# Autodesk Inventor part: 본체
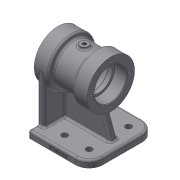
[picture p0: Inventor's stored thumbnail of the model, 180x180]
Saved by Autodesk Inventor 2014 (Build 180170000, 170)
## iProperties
Created: 2020-06
Part Number: 본체
Material: Generic
Document SubType Name: Modeling
Designer: kh
Density: 1 g/cm^3
Appearance: Default
Author: kh
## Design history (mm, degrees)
sketch "Sketch1"
  geometry: L1 (-45, -49)-(45, -49); L2 (45, -49)-(45, 49); L3 (45, 49)-(-45, 49); L4 (-45, 49)-(-45, -49); L5 (-45, -49)-(45, 49); L6 (45, -49)-(-45, 49); 1 further point
  constraints: 12 end point, 2 midpoint, 2 parallel, 1 horizontal, 1 perpendicular
  dimensions: "d0" = 98 distance between parallel lines of L1 L3; "d1" = 90 distance between parallel lines of L2 L4
extrude "Extrusion1" new body sketch "Sketch1" distance "d2" = 10; taper "d3" = 0 deg
sketch "Sketch2"
  geometry: L1 (0, 98)-(0, 0) reference; L2 (0, 98)-(10, 98) reference; L3 (80, 84)-(80, 14); L4 (80, 84)-(7, 84); L5 (7, 84)-(7, 14); L6 (7, 14)-(80, 14); 3 further points
  constraints: 8 end point, 3 perpendicular, 2 midpoint, 1 horizontal alignment, 1 parallel
  dimensions: "d4" = 80 distance from line of L3 point (0, 49); "d5" = 70 distance of L3.end L3.start
extrude "Extrusion2" join sketch "Sketch2" distance "d6" = 10; taper "d7" = 0 deg
sketch "Sketch3"
  geometry: L1 (-3.882, 90)-(-33, 10); L2 (-45, 0)-(45, 0) reference; L3 (35, 10)-(45, 10) reference; L4 (45, 10)-(-45, 10) reference; L5 (-45, 10)-(45, 10) reference; L6 (45, 10)-(35, 10) reference; L7 (-3.882, 90)-(40, 90); L8 (40, 90)-(40, 10); L9 (-33, 10)-(40, 10); 1 further point
  constraints: 8 end point, 1 collinear, 1 midpoint, 1 parallel, 1 point on line
  dimensions: "d8" = 12 distance of L1.end L4.end; "d9" = 70 deg angle of L4 L1; "d10" = 80 vertical distance of L1.start L1.end
extrude "Extrusion3" join sketch "Sketch3" stored distance "d11" = 10; taper "d12" = 0 deg
sketch "Sketch4"
  geometry: L1 (50, 115)-(28, 115); L2 (28, 115)-(28, 109); L3 (28, 109)-(-6, 109); L4 (-6, 109)-(-6, 115); L5 (-6, 115)-(-28, 115); L6 (-45, 0)-(45, 0) reference; L7 (45, 0)-(45, 10) reference; L8 (-45, 10)-(45, 10) reference; L9 (-45, 0)-(-45, 10) reference; L10 (50, 80)-(-28, 80); L11 (50, 115)-(50, 80); L12 (-28, 115)-(-28, 80); 4 further points
  constraints: 16 end point, 3 parallel, 3 perpendicular, 2 midpoint, 1 collinear, 1 horizontal, 1 point on line, 1 vertical alignment
  dimensions: "d13" = 78 distance of L5.end L1.start; "d14" = 22 distance of L1.end L1.start; "d15" = 22 distance of L5.end L4.end; "d16" = 5 distance from line of L7 L1.start; "d19" = 80 distance between parallel lines of L6 L10; "d20" = 70 diameter of L1 L10; "d21" = 70 diameter of L5 L10; "d22" = 58 diameter of L3 L10
revolve "Revolution1" sketch "Sketch4" stored, may be unused: angle "d23" = 90 deg
sketch "Sketch5"
  geometry: L1 (56, 80)-(-56, 80); L2 (-45, 0)-(45, 0) reference; L3 (50, 103.5)-(32, 103.5); L4 (32, 103.5)-(32, 100); L5 (32, 100)-(26, 100); L6 (26, 100)-(26, 103); L7 (26, 103)-(-4, 103); L8 (-4, 103)-(-4, 100); L9 (-4, 100)-(-10, 100); L10 (-10, 100)-(-10, 103.5); L11 (-10, 103.5)-(-28, 103.5); L12 (28, 51.434)-(-6, 51.434) reference; L13 (28, 51.434)-(28, 51.434) reference; L14 (-6, 51.434)-(28, 51.434) reference; L15 (-6, 51.434)-(-6, 51.434) reference; L16 (50, 45)-(50, 115) reference; L17 (35, 45.359)-(28, 45.359) reference; L18 (35, 80)-(35, 45.359) reference; L19 (45, 80)-(35, 80) reference; L20 (45, 80)-(45, 80) reference; L21 (45, 80)-(35, 80) reference; L22 (35, 45.359)-(35, 80) reference; L23 (28, 45.359)-(35, 45.359) reference; L24 (28, 45.359)-(28, 45.359) reference; L25 (-6, 45.359)-(-20.13, 45.359) reference; L26 (-6, 45.359)-(-6, 45.359) reference; L27 (-20.13, 45.359)-(-6, 45.359) reference; L28 (-20.13, 45.359)-(-20.13, 45.359) reference; L29 (-28, 45)-(-28, 115) reference; L30 (50, 103.5)-(50, 80); L31 (-28, 103.5)-(-28, 80); L32 (50, 80)-(-28, 80); 2 further points
  constraints: 26 end point, 5 perpendicular, 4 parallel, 3 midpoint, 2 point on line, 1 collinear, 1 horizontal, 1 vertical alignment
  dimensions: "d24" = 80 distance between parallel lines of L2 L1; "d25" = 47 diameter of L3 L1; "d26" = 47 diameter of L11 L1; "d27" = 46 diameter of L7 L1; "d28" = 40 diameter of L5 L1; "d29" = 40 diameter of L9 L1; "d30" = 18 distance of L3.start L3.end; "d31" = 18 distance of L10.end L11.end; "d32" = 30 distance of L6.end L7.end; "d33" = 6 distance of L4.end L5.end
revolve "Revolution2" sketch "Sketch5" stored, may be unused: angle "d34" = 90 deg
sketch "Sketch6"
  geometry: C1 r 23.5 at (0, 0) reference; 2 further points
  constraints: 1 horizontal alignment
  dimensions: "d35" = 28.5 distance of C1.centre point (28.5, 0)
hole "Hole1" sketch "Sketch6" at (28.5, 0) diameter "d36" = 3.242; stored, may be unused: countersink angle "d40" = 90 deg, drill point angle "d42" = 118 deg; dims "d37" = 10, "d38" = 4, "d39" = 2, "d41" = 12
pattern_circular "Circular Pattern1" dims angle "d44" = 360 deg
sketch "Sketch7"
  geometry: C1 r 23.5 at (0, 0) reference; 2 further points
  constraints: 1 horizontal alignment
  dimensions: "d46" = 28.5 distance of C1.centre point (-28.5, 0)
hole "Hole2" sketch "Sketch7" at (-28.5, 0) diameter "d47" = 3.242; stored, may be unused: countersink angle "d51" = 90 deg, drill point angle "d53" = 118 deg; dims "d48" = 10, "d49" = 4, "d50" = 2, "d52" = 12
pattern_circular "Circular Pattern2" dims angle "d55" = 360 deg
workplane "Work Plane1"
sketch "Sketch8"
  geometry: L1 (17, 5)-(-17, 5) reference; L2 (17, -5)-(17, 5) reference; L3 (-17, -5)-(17, -5) reference; L4 (-17, -5)-(-17, 5) reference; C1 r 6 at (0, 0); 2 further points
  constraints: 1 centre point, 1 midpoint, 1 vertical alignment
  dimensions: "d57" = 12 diameter of C1
extrude "Extrusion4" join sketch "Sketch8" stored distance "d58" = 6; taper "d59" = 0 deg
hole "Hole3" diameter "d62" = 5.188; stored, may be unused: countersink angle "d66" = 90 deg, drill point angle "d68" = 0 deg; dims "d60" = 10, "d61" = 10, "d63" = 10, "d64" = 4, "d65" = 2, "d67" = 12
sketch "Sketch9"
  geometry: L1 (-45, -35)-(-45, -49) reference; L2 (-45, 49)-(-45, 35) reference; L3 (-45, -49)-(45, -49) reference; L4 (45, 49)-(-45, 49) reference; 5 further points
  dimensions: "d69" = 70 distance from line of point (25, 29) L2; "d70" = 70 distance from line of point (25, -29) L1; "d71" = 36 distance of point (25, 29) point (-11, 29); "d72" = 36 distance of point (25, -29) point (-11, -29); "d73" = 58 distance of point (25, -29) point (25, 29); "d107" = 20 distance from line of L4 point (25, 29); "d108" = 20 distance from line of L4 point (-11, 29); "d109" = 20 distance from line of L3 point (-11, -29)
hole "Hole4" sketch "Sketch9" at (25, 29), (25, -29), (-11, -29), (-11, 29) diameter "d74" = 9; stored, may be unused: countersink angle "d78" = 90 deg, drill point angle "d80" = 0 deg; dims "d75" = 10, "d76" = 4, "d77" = 2, "d79" = 12
sketch "Sketch10"
  geometry: L1 (0, 0)-(90, 0) reference; L2 (0, 0)-(0, 10) reference; 2 further points
  constraints: 1 other
  dimensions: "d81" = 45 distance from line of point (45, 4) L2; "d82" = 4 distance from line of L1 point (45, 4)
emboss "Emboss1" sketch "Sketch10" dims "d0" = 98, "d1" = 90, "d83" = 0.5, "d84" = 0
fillet "Fillet1" dims "d85" = 0.3
fillet "Fillet2" dims "d86" = 3
fillet "Fillet3" dims "d87" = 3
fillet "Fillet4" dims "d88" = 3
fillet "Fillet6" dims "d90" = 3
fillet "Fillet7" dims "d91" = 3
fillet "Fillet8" dims "d92" = 3
chamfer "Chamfer1" distance "d93" = 1; stored, may be unused: second distance "d94" = 2, angle "d95" = 45 deg
hole "Hole5" diameter "d98" = 5.188; stored, may be unused: countersink angle "d102" = 90 deg, drill point angle "d104" = 0 deg; dims "d96" = 10, "d97" = 10, "d99" = 10, "d100" = 4, "d101" = 2, "d103" = 12
fillet "Fillet10" dims "d106" = 3
fillet "Fillet11" dims "d110" = 20
fillet "Fillet12" dims "d111" = 3
fillet "Fillet13" dims "d112" = 3
body "Solid1"
node "Projected Loop1"
node "Projected Loop2"
node "Projected Loop3"
node "Projected Loop4"
node "Projected Loop5"
node "Projected Loop6"
